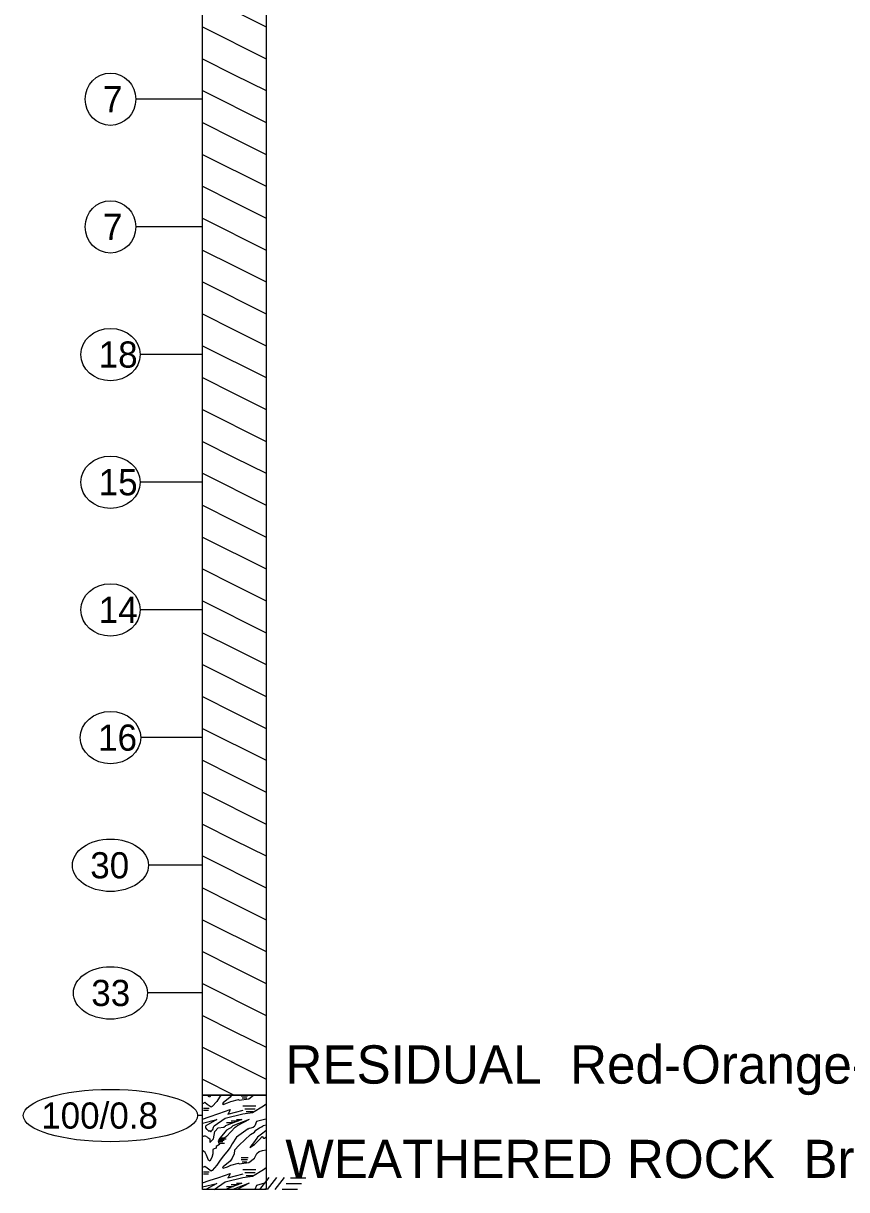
# Model space of a CAD drawing. Extents: x -26 to 303, y -74 to 518.
# Drawn here: x 126.74 to 158.98, y -74.2 to -28.53 of the extents above; entities that cross this region are included whole.
import ezdxf

# ---------------------------------------------------------------- set-up
doc = ezdxf.new("R2010")
doc.units = 0
for name, color, linetype in [('Prop Road Sect_ Boring - Material (Desc Tx)', 7, 'Continuous'), ('Prop Road Sect_ Boring - Material (Outline)', 7, 'Continuous'), ('Prop Road Sect_ Boring - Peripheral (HR Indicator)', 7, 'Continuous'), ('Prop Road Sect_ Boring - Peripheral (SPT Oval + Leader)', 7, 'Continuous'), ('Prop Road Sect_ Boring - Peripheral (SPT Tx)', 7, 'Continuous')]:
    doc.layers.add(name, color=color, linetype=linetype)

msp = doc.modelspace()

# ---------------------------------------------------------------- linework, layer by layer
at = {"layer": 'Prop Road Sect_ Boring - Material (Outline)'}
for p, q in [((134.999, -28.042), (136.248, -28.667)), ((134.999, -28.042), (136.248, -28.667)), ((133.75, -28.667), (136.248, -29.916)), ((133.75, -28.667), (136.248, -29.916)), ((133.75, -28.667), (136.248, -29.916)), ((133.75, -28.667), (136.248, -29.916)), ((136.248, -28.667), (136.25, -28.668)), ((136.248, -28.667), (136.25, -28.668)), ((136.248, -28.667), (136.25, -28.668)), ((136.248, -28.667), (136.25, -28.668)), ((133.75, -29.916), (134.999, -30.54)), ((133.75, -29.916), (134.999, -30.54)), ((136.248, -29.916), (136.25, -29.917)), ((136.248, -29.916), (136.25, -29.917)), ((134.999, -30.54), (136.248, -31.164)), ((134.999, -30.54), (136.248, -31.164)), ((133.75, -31.164), (136.248, -32.413)), ((133.75, -31.164), (136.248, -32.413)), ((133.75, -31.164), (136.248, -32.413)), ((133.75, -31.164), (136.248, -32.413)), ((136.248, -31.164), (136.25, -31.166)), ((136.248, -31.164), (136.25, -31.166)), ((136.248, -31.164), (136.25, -31.166)), ((136.248, -31.164), (136.25, -31.166)), ((133.75, -32.413), (134.999, -33.037)), ((133.75, -32.413), (134.999, -33.037)), ((136.248, -32.413), (136.25, -32.414)), ((136.248, -32.413), (136.25, -32.414)), ((134.999, -33.037), (136.248, -33.662)), ((134.999, -33.037), (136.248, -33.662)), ((133.75, -33.662), (136.248, -34.911)), ((133.75, -33.662), (136.248, -34.911)), ((133.75, -33.662), (136.248, -34.911)), ((133.75, -33.662), (136.248, -34.911)), ((136.248, -33.662), (136.25, -33.663)), ((136.248, -33.662), (136.25, -33.663)), ((136.248, -33.662), (136.25, -33.663)), ((136.248, -33.662), (136.25, -33.663)), ((133.75, -34.911), (134.999, -35.535)), ((133.75, -34.911), (134.999, -35.535)), ((136.248, -34.911), (136.25, -34.912)), ((136.248, -34.911), (136.25, -34.912)), ((134.999, -35.535), (136.248, -36.159)), ((134.999, -35.535), (136.248, -36.159)), ((133.75, -36.159), (136.248, -37.408)), ((133.75, -36.159), (136.248, -37.408)), ((133.75, -36.159), (136.248, -37.408)), ((133.75, -36.159), (136.248, -37.408)), ((136.248, -36.159), (136.25, -36.161)), ((136.248, -36.159), (136.25, -36.161)), ((136.248, -36.159), (136.25, -36.161)), ((136.248, -36.159), (136.25, -36.161)), ((133.75, -37.408), (134.999, -38.032)), ((133.75, -37.408), (134.999, -38.032)), ((136.248, -37.408), (136.25, -37.409)), ((136.248, -37.408), (136.25, -37.409)), ((134.999, -38.032), (136.248, -38.657)), ((134.999, -38.032), (136.248, -38.657)), ((133.75, -38.657), (136.248, -39.906)), ((133.75, -38.657), (136.248, -39.906)), ((133.75, -38.657), (136.248, -39.906)), ((133.75, -38.657), (136.248, -39.906)), ((136.248, -38.657), (136.25, -38.658)), ((136.248, -38.657), (136.25, -38.658)), ((136.248, -38.657), (136.25, -38.658)), ((136.248, -38.657), (136.25, -38.658)), ((133.75, -39.906), (134.999, -40.53)), ((133.75, -39.906), (134.999, -40.53)), ((136.248, -39.906), (136.25, -39.907)), ((136.248, -39.906), (136.25, -39.907)), ((134.999, -40.53), (136.248, -41.154)), ((134.999, -40.53), (136.248, -41.154)), ((133.75, -41.154), (136.248, -42.403)), ((133.75, -41.154), (136.248, -42.403)), ((133.75, -41.154), (136.248, -42.403)), ((133.75, -41.154), (136.248, -42.403)), ((136.248, -41.154), (136.25, -41.156)), ((136.248, -41.154), (136.25, -41.156)), ((136.248, -41.154), (136.25, -41.156)), ((136.248, -41.154), (136.25, -41.156)), ((133.75, -42.403), (134.999, -43.027)), ((133.75, -42.403), (134.999, -43.027)), ((136.248, -42.403), (136.25, -42.404)), ((136.248, -42.403), (136.25, -42.404)), ((134.999, -43.027), (136.248, -43.652)), ((134.999, -43.027), (136.248, -43.652)), ((133.75, -43.652), (136.248, -44.901)), ((133.75, -43.652), (136.248, -44.901)), ((133.75, -43.652), (136.248, -44.901)), ((133.75, -43.652), (136.248, -44.901)), ((136.248, -43.652), (136.25, -43.653)), ((136.248, -43.652), (136.25, -43.653)), ((136.248, -43.652), (136.25, -43.653)), ((136.248, -43.652), (136.25, -43.653)), ((133.75, -44.901), (134.999, -45.525)), ((133.75, -44.901), (134.999, -45.525)), ((136.248, -44.901), (136.25, -44.902)), ((136.248, -44.901), (136.25, -44.902)), ((134.999, -45.525), (136.248, -46.149)), ((134.999, -45.525), (136.248, -46.149)), ((133.75, -46.149), (136.248, -47.398)), ((133.75, -46.149), (136.248, -47.398)), ((133.75, -46.149), (136.248, -47.398)), ((133.75, -46.149), (136.248, -47.398)), ((136.248, -46.149), (136.25, -46.151)), ((136.248, -46.149), (136.25, -46.151)), ((136.248, -46.149), (136.25, -46.151)), ((136.248, -46.149), (136.25, -46.151)), ((133.75, -47.398), (134.999, -48.022)), ((133.75, -47.398), (134.999, -48.022)), ((136.248, -47.398), (136.25, -47.399)), ((136.248, -47.398), (136.25, -47.399)), ((134.999, -48.022), (136.248, -48.647)), ((134.999, -48.022), (136.248, -48.647)), ((133.75, -48.647), (136.248, -49.896)), ((133.75, -48.647), (136.248, -49.896)), ((133.75, -48.647), (136.248, -49.896)), ((133.75, -48.647), (136.248, -49.896)), ((136.248, -48.647), (136.25, -48.648)), ((136.248, -48.647), (136.25, -48.648)), ((136.248, -48.647), (136.25, -48.648)), ((136.248, -48.647), (136.25, -48.648)), ((133.75, -49.896), (134.999, -50.52)), ((133.75, -49.896), (134.999, -50.52)), ((136.248, -49.896), (136.25, -49.897)), ((136.248, -49.896), (136.25, -49.897)), ((134.999, -50.52), (136.248, -51.144)), ((134.999, -50.52), (136.248, -51.144)), ((133.75, -51.144), (136.248, -52.393)), ((133.75, -51.144), (136.248, -52.393)), ((133.75, -51.144), (136.248, -52.393)), ((133.75, -51.144), (136.248, -52.393)), ((136.248, -51.144), (136.25, -51.146)), ((136.248, -51.144), (136.25, -51.146)), ((136.248, -51.144), (136.25, -51.146)), ((136.248, -51.144), (136.25, -51.146)), ((133.75, -52.393), (134.999, -53.017)), ((133.75, -52.393), (134.999, -53.017)), ((136.248, -52.393), (136.25, -52.394)), ((136.248, -52.393), (136.25, -52.394)), ((134.999, -53.017), (136.248, -53.642)), ((134.999, -53.017), (136.248, -53.642)), ((133.75, -53.642), (136.248, -54.891)), ((133.75, -53.642), (136.248, -54.891)), ((133.75, -53.642), (136.248, -54.891)), ((133.75, -53.642), (136.248, -54.891)), ((136.248, -53.642), (136.25, -53.643)), ((136.248, -53.642), (136.25, -53.643)), ((136.248, -53.642), (136.25, -53.643)), ((136.248, -53.642), (136.25, -53.643)), ((133.75, -54.891), (134.999, -55.515)), ((133.75, -54.891), (134.999, -55.515)), ((136.248, -54.891), (136.25, -54.892)), ((136.248, -54.891), (136.25, -54.892)), ((134.999, -55.515), (136.248, -56.139)), ((134.999, -55.515), (136.248, -56.139)), ((133.75, -56.139), (136.248, -57.388)), ((133.75, -56.139), (136.248, -57.388)), ((133.75, -56.139), (136.248, -57.388)), ((133.75, -56.139), (136.248, -57.388)), ((136.248, -56.139), (136.25, -56.141)), ((136.248, -56.139), (136.25, -56.141)), ((136.248, -56.139), (136.25, -56.141)), ((136.248, -56.139), (136.25, -56.141)), ((133.75, -57.388), (134.999, -58.012)), ((133.75, -57.388), (134.999, -58.012)), ((136.248, -57.388), (136.25, -57.389)), ((136.248, -57.388), (136.25, -57.389)), ((134.999, -58.012), (136.248, -58.637)), ((134.999, -58.012), (136.248, -58.637)), ((133.75, -58.637), (136.248, -59.886)), ((133.75, -58.637), (136.248, -59.886)), ((133.75, -58.637), (136.248, -59.886)), ((133.75, -58.637), (136.248, -59.886)), ((136.248, -58.637), (136.25, -58.638)), ((136.248, -58.637), (136.25, -58.638)), ((136.248, -58.637), (136.25, -58.638)), ((136.248, -58.637), (136.25, -58.638)), ((133.75, -59.886), (134.999, -60.51)), ((133.75, -59.886), (134.999, -60.51)), ((136.248, -59.886), (136.25, -59.887)), ((136.248, -59.886), (136.25, -59.887)), ((134.999, -60.51), (136.248, -61.134)), ((134.999, -60.51), (136.248, -61.134)), ((133.75, -61.134), (136.248, -62.383)), ((133.75, -61.134), (136.248, -62.383)), ((133.75, -61.134), (136.248, -62.383)), ((133.75, -61.134), (136.248, -62.383)), ((136.248, -61.134), (136.25, -61.136)), ((136.248, -61.134), (136.25, -61.136)), ((136.248, -61.134), (136.25, -61.136)), ((136.248, -61.134), (136.25, -61.136)), ((133.75, -62.383), (134.999, -63.007)), ((133.75, -62.383), (134.999, -63.007)), ((136.248, -62.383), (136.25, -62.384)), ((136.248, -62.383), (136.25, -62.384)), ((134.999, -63.007), (136.248, -63.632)), ((134.999, -63.007), (136.248, -63.632)), ((133.75, -63.632), (136.248, -64.881)), ((133.75, -63.632), (136.248, -64.881)), ((133.75, -63.632), (136.248, -64.881)), ((133.75, -63.632), (136.248, -64.881)), ((136.248, -63.632), (136.25, -63.633)), ((136.248, -63.632), (136.25, -63.633)), ((136.248, -63.632), (136.25, -63.633)), ((136.248, -63.632), (136.25, -63.633)), ((133.75, -64.881), (134.999, -65.505)), ((133.75, -64.881), (134.999, -65.505)), ((136.248, -64.881), (136.25, -64.882)), ((136.248, -64.881), (136.25, -64.882)), ((134.999, -65.505), (136.248, -66.129)), ((134.999, -65.505), (136.248, -66.129)), ((133.75, -66.129), (136.248, -67.378)), ((133.75, -66.129), (136.248, -67.378)), ((133.75, -66.129), (136.248, -67.378)), ((133.75, -66.129), (136.248, -67.378)), ((136.248, -66.129), (136.25, -66.131)), ((136.248, -66.129), (136.25, -66.131)), ((136.248, -66.129), (136.25, -66.131)), ((136.248, -66.129), (136.25, -66.131)), ((133.75, -67.378), (134.999, -68.002)), ((133.75, -67.378), (134.999, -68.002)), ((136.248, -67.378), (136.25, -67.379)), ((136.248, -67.378), (136.25, -67.379)), ((134.999, -68.002), (136.248, -68.627)), ((134.999, -68.002), (136.248, -68.627)), ((133.75, -68.627), (136.248, -69.876)), ((133.75, -68.627), (136.248, -69.876)), ((133.75, -68.627), (136.248, -69.876)), ((133.75, -68.627), (136.248, -69.876)), ((136.248, -68.627), (136.25, -68.628)), ((136.248, -68.627), (136.25, -68.628)), ((136.248, -68.627), (136.25, -68.628)), ((136.248, -68.627), (136.25, -68.628)), ((133.75, -69.876), (134.999, -70.5)), ((133.75, -69.876), (134.999, -70.5)), ((136.248, -69.876), (136.25, -69.877)), ((136.248, -69.876), (136.25, -69.877)), ((135.264, -70.526), (135.514, -70.526)), ((135.264, -70.526), (135.514, -70.526)), ((135.314, -70.611), (135.489, -70.611)), ((135.314, -70.611), (135.489, -70.611)), ((133.789, -71.005), (134.014, -71.005)), ((133.789, -71.005), (134.014, -71.005)), ((133.789, -71.089), (133.989, -71.089)), ((133.789, -71.089), (133.989, -71.089)), ((135.339, -70.92), (135.839, -70.92)), ((135.339, -70.92), (135.839, -70.92)), ((135.414, -71.032), (135.814, -71.032)), ((135.414, -71.032), (135.814, -71.032)), ((135.464, -71.145), (135.739, -71.145)), ((135.464, -71.145), (135.739, -71.145)), ((136.25, -70.842), (136.248, -70.843)), ((136.25, -70.842), (136.248, -70.843)), ((133.75, -71.596), (134.318, -71.459)), ((133.75, -71.596), (134.318, -71.459)), ((134.318, -71.459), (133.889, -71.702)), ((134.318, -71.459), (133.889, -71.702)), ((134.189, -71.759), (134.21, -71.702)), ((134.189, -71.759), (134.21, -71.702)), ((134.589, -71.759), (134.649, -71.702)), ((134.589, -71.759), (134.649, -71.702)), ((135.289, -71.456), (134.649, -71.702)), ((135.289, -71.456), (134.649, -71.702)), ((134.688, -71.577), (134.974, -71.577)), ((134.688, -71.577), (134.974, -71.577)), ((134.873, -71.509), (135.152, -71.509)), ((134.873, -71.509), (135.152, -71.509)), ((135.585, -71.456), (134.944, -71.702)), ((135.585, -71.456), (134.944, -71.702)), ((135.039, -71.759), (135.107, -71.702)), ((135.039, -71.759), (135.107, -71.702)), ((135.089, -71.456), (135.289, -71.456)), ((135.089, -71.456), (135.289, -71.456)), ((135.585, -71.456), (135.107, -71.702)), ((135.585, -71.456), (135.107, -71.702)), ((136.248, -71.673), (136.134, -71.702)), ((136.248, -71.673), (136.134, -71.702)), ((136.248, -71.438), (136.25, -71.437)), ((136.248, -71.438), (136.25, -71.437)), ((136.248, -71.596), (136.25, -71.595)), ((136.248, -71.596), (136.25, -71.595)), ((136.25, -72.132), (136.248, -72.133)), ((136.25, -72.132), (136.248, -72.133)), ((134.371, -72.316), (134.556, -72.316)), ((134.371, -72.316), (134.556, -72.316)), ((134.388, -72.261), (134.603, -72.261)), ((134.388, -72.261), (134.603, -72.261)), ((134.389, -72.377), (134.614, -72.377)), ((134.389, -72.377), (134.614, -72.377)), ((134.419, -72.214), (134.686, -72.214)), ((134.419, -72.214), (134.686, -72.214)), ((133.856, -72.749), (133.75, -72.663)), ((133.856, -72.749), (133.75, -72.663)), ((135.264, -72.94), (135.539, -72.94)), ((135.264, -72.94), (135.539, -72.94)), ((135.264, -73.024), (135.514, -73.024)), ((135.264, -73.024), (135.514, -73.024)), ((136.25, -72.665), (136.248, -72.663)), ((136.25, -72.665), (136.248, -72.663)), ((133.789, -73.502), (134.014, -73.502)), ((133.789, -73.502), (134.014, -73.502)), ((135.314, -73.109), (135.489, -73.109)), ((135.314, -73.109), (135.489, -73.109)), ((135.339, -73.417), (135.839, -73.417)), ((135.339, -73.417), (135.839, -73.417)), ((135.414, -73.53), (135.814, -73.53)), ((135.414, -73.53), (135.814, -73.53)), ((136.25, -73.339), (136.248, -73.34)), ((136.25, -73.339), (136.248, -73.34)), ((133.75, -74.093), (134.318, -73.956)), ((133.75, -74.093), (134.318, -73.956)), ((133.789, -73.586), (133.989, -73.586)), ((133.789, -73.586), (133.989, -73.586)), ((134.318, -73.956), (133.889, -74.2)), ((134.318, -73.956), (133.889, -74.2)), ((135.289, -73.953), (134.649, -74.2)), ((135.289, -73.953), (134.649, -74.2)), ((135.585, -73.953), (134.944, -74.2)), ((135.585, -73.953), (134.944, -74.2)), ((135.089, -73.953), (135.289, -73.953)), ((135.089, -73.953), (135.289, -73.953)), ((135.585, -73.953), (135.107, -74.2)), ((135.585, -73.953), (135.107, -74.2)), ((135.464, -73.642), (135.739, -73.642)), ((135.464, -73.642), (135.739, -73.642)), ((136.248, -73.936), (136.25, -73.935)), ((136.248, -73.936), (136.25, -73.935)), ((134.688, -74.075), (134.974, -74.075)), ((134.688, -74.075), (134.974, -74.075)), ((134.873, -74.006), (135.152, -74.006)), ((134.873, -74.006), (135.152, -74.006)), ((136.248, -74.171), (136.134, -74.2)), ((136.248, -74.171), (136.134, -74.2)), ((136.248, -74.093), (136.25, -74.092)), ((136.248, -74.093), (136.25, -74.092))]:
    msp.add_line(p, q, dxfattribs=at)
for points in [[(133.75, -15.5), (136.25, -15.5), (136.25, -70.5), (133.75, -70.5)], [(133.75, -70.5), (136.25, -70.5), (136.25, -74.2), (133.75, -74.2)]]:
    msp.add_lwpolyline(points, close=True, dxfattribs=at)
for points in [[(134.477, -70.5), (134.414, -70.582), (134.314, -70.751), (134.139, -70.949), (134.089, -70.976), (133.939, -70.864)], [(134.477, -70.5), (134.414, -70.582), (134.314, -70.751), (134.139, -70.949), (134.089, -70.976), (133.939, -70.864)], [(134.083, -70.5), (134.039, -70.582), (133.989, -70.555), (133.968, -70.5)], [(134.083, -70.5), (134.039, -70.582), (133.989, -70.555), (133.968, -70.5)], [(134.894, -70.5), (134.839, -70.582), (134.564, -70.807), (134.539, -70.836), (134.564, -70.864), (134.739, -70.807), (134.864, -70.751), (135.164, -70.667), (135.189, -70.695), (135.564, -70.639), (135.749, -70.5)], [(134.894, -70.5), (134.839, -70.582), (134.564, -70.807), (134.539, -70.836), (134.564, -70.864), (134.739, -70.807), (134.864, -70.751), (135.164, -70.667), (135.189, -70.695), (135.564, -70.639), (135.749, -70.5)], [(133.939, -70.864), (133.846, -70.794), (133.75, -70.843)], [(133.939, -70.864), (133.846, -70.794), (133.75, -70.843)], [(133.75, -71.438), (134.018, -71.345), (134.396, -71.222), (134.843, -71.069), (134.788, -71.191), (134.745, -71.242), (135.342, -71.087)], [(133.75, -71.438), (134.018, -71.345), (134.396, -71.222), (134.843, -71.069), (134.788, -71.191), (134.745, -71.242), (135.342, -71.087)], [(134.21, -71.702), (134.639, -71.399), (135.339, -71.23), (135.714, -71.174), (136.139, -70.92), (136.248, -70.841)], [(134.21, -71.702), (134.639, -71.399), (135.339, -71.23), (135.714, -71.174), (136.139, -70.92), (136.248, -70.841)], [(133.939, -71.842), (133.889, -71.786), (133.889, -71.702)], [(133.939, -71.842), (133.889, -71.786), (133.889, -71.702)], [(134.944, -71.702), (134.858, -71.782), (134.81, -71.806), (134.698, -71.877), (134.624, -71.954), (134.51, -72.091), (134.439, -72.18)], [(134.944, -71.702), (134.858, -71.782), (134.81, -71.806), (134.698, -71.877), (134.624, -71.954), (134.51, -72.091), (134.439, -72.18)], [(135.539, -71.815), (135.586, -71.796), (135.656, -71.781), (135.743, -71.754), (135.798, -71.702)], [(135.539, -71.815), (135.586, -71.796), (135.656, -71.781), (135.743, -71.754), (135.798, -71.702)], [(136.248, -71.44), (136.189, -71.455), (135.864, -71.539), (135.798, -71.702)], [(136.248, -71.44), (136.189, -71.455), (135.864, -71.539), (135.798, -71.702)], [(136.039, -71.759), (136.071, -71.741), (136.134, -71.702)], [(136.039, -71.759), (136.071, -71.741), (136.134, -71.702)], [(133.968, -72.159), (133.87, -72.11), (133.803, -72.11), (133.75, -72.133)], [(133.968, -72.159), (133.87, -72.11), (133.803, -72.11), (133.75, -72.133)], [(135.039, -71.759), (134.689, -72.124), (134.614, -72.18), (134.439, -72.18), (134.364, -72.292), (134.389, -72.377), (134.414, -72.434), (134.289, -72.517), (134.289, -72.574), (134.289, -72.574), (134.214, -72.602), (134.164, -72.63), (134.164, -72.799), (134.114, -72.94), (134.039, -73.08), (133.989, -73.052), (133.914, -72.855), (133.856, -72.749)], [(135.039, -71.759), (134.689, -72.124), (134.614, -72.18), (134.439, -72.18), (134.364, -72.292), (134.389, -72.377), (134.414, -72.434), (134.289, -72.517), (134.289, -72.574), (134.289, -72.574), (134.214, -72.602), (134.164, -72.63), (134.164, -72.799), (134.114, -72.94), (134.039, -73.08), (133.989, -73.052), (133.914, -72.855), (133.856, -72.749)], [(133.939, -71.842), (133.964, -71.871), (134.014, -71.927), (134.039, -71.871), (134.064, -71.927), (134.089, -71.927), (134.114, -71.871), (134.164, -71.842), (134.189, -71.759)], [(133.939, -71.842), (133.964, -71.871), (134.014, -71.927), (134.039, -71.871), (134.064, -71.927), (134.089, -71.927), (134.114, -71.871), (134.164, -71.842), (134.189, -71.759)], [(135.539, -71.815), (135.089, -72.152), (134.914, -72.405), (134.839, -72.546), (134.714, -72.715), (134.564, -72.884), (134.414, -73.08), (134.314, -73.249), (134.139, -73.446), (134.089, -73.474), (133.939, -73.361)], [(135.539, -71.815), (135.089, -72.152), (134.914, -72.405), (134.839, -72.546), (134.714, -72.715), (134.564, -72.884), (134.414, -73.08), (134.314, -73.249), (134.139, -73.446), (134.089, -73.474), (133.939, -73.361)], [(133.968, -72.159), (134.039, -72.209), (134.039, -72.349), (134.189, -72.209), (134.239, -71.927), (134.364, -71.786), (134.589, -71.759)], [(133.968, -72.159), (134.039, -72.209), (134.039, -72.349), (134.189, -72.209), (134.239, -71.927), (134.364, -71.786), (134.589, -71.759)], [(135.639, -72.04), (135.189, -72.461), (135.014, -72.659), (134.989, -72.799), (134.914, -72.967), (134.839, -73.08), (134.564, -73.305), (134.539, -73.334), (134.564, -73.361), (134.739, -73.305), (134.864, -73.249), (135.164, -73.165), (135.189, -73.192), (135.564, -73.136), (135.789, -72.967), (135.886, -72.792)], [(135.639, -72.04), (135.189, -72.461), (135.014, -72.659), (134.989, -72.799), (134.914, -72.967), (134.839, -73.08), (134.564, -73.305), (134.539, -73.334), (134.564, -73.361), (134.739, -73.305), (134.864, -73.249), (135.164, -73.165), (135.189, -73.192), (135.564, -73.136), (135.789, -72.967), (135.886, -72.792)], [(136.248, -71.883), (136.114, -71.984), (135.914, -72.152), (135.789, -72.321), (135.614, -72.546), (135.789, -72.434), (135.989, -72.236), (136.089, -72.124), (136.139, -72.18), (136.189, -72.18), (136.248, -72.128)], [(136.248, -71.883), (136.114, -71.984), (135.914, -72.152), (135.789, -72.321), (135.614, -72.546), (135.789, -72.434), (135.989, -72.236), (136.089, -72.124), (136.139, -72.18), (136.189, -72.18), (136.248, -72.128)], [(135.639, -72.04), (135.789, -71.955), (135.839, -71.871), (135.989, -71.786), (136.039, -71.759)], [(135.639, -72.04), (135.789, -71.955), (135.839, -71.871), (135.989, -71.786), (136.039, -71.759)], [(135.886, -72.792), (135.969, -72.71), (136.11, -72.672), (136.248, -72.646)], [(135.886, -72.792), (135.969, -72.71), (136.11, -72.672), (136.248, -72.646)], [(133.939, -73.361), (133.846, -73.291), (133.75, -73.34)], [(133.939, -73.361), (133.846, -73.291), (133.75, -73.34)], [(134.21, -74.2), (134.639, -73.896), (135.339, -73.727), (135.714, -73.671), (136.139, -73.417), (136.248, -73.339)], [(134.21, -74.2), (134.639, -73.896), (135.339, -73.727), (135.714, -73.671), (136.139, -73.417), (136.248, -73.339)], [(133.75, -73.936), (134.018, -73.842), (134.396, -73.72), (134.843, -73.566), (134.788, -73.689), (134.745, -73.74), (135.342, -73.584)], [(133.75, -73.936), (134.018, -73.842), (134.396, -73.72), (134.843, -73.566), (134.788, -73.689), (134.745, -73.74), (135.342, -73.584)], [(136.248, -73.938), (136.189, -73.952), (135.864, -74.036), (135.798, -74.2)], [(136.248, -73.938), (136.189, -73.952), (135.864, -74.036), (135.798, -74.2)]]:
    msp.add_lwpolyline(points, dxfattribs=at)
at = {"layer": 'Prop Road Sect_ Boring - Peripheral (HR Indicator)'}
for p, q in [((136, -74.2), (136.361, -73.721)), ((136.3, -74.2), (136.661, -73.721)), ((136.6, -74.2), (136.961, -73.721)), ((137.037, -73.961), (137.637, -73.961)), ((137.205, -73.738), (137.805, -73.738)), ((136.869, -74.183), (137.469, -74.183))]:
    msp.add_line(p, q, dxfattribs=at)
at = {"layer": 'Prop Road Sect_ Boring - Peripheral (SPT Oval + Leader)'}
for p, q in [((133.75, -31.5), (131.141, -31.5)), ((133.75, -36.5), (131.141, -36.5)), ((133.75, -41.5), (131.31, -41.5)), ((133.75, -46.5), (131.31, -46.5)), ((133.75, -51.5), (131.31, -51.5)), ((133.75, -56.5), (131.334, -56.5)), ((133.75, -61.5), (131.641, -61.5)), ((133.75, -66.5), (131.601, -66.5)), ((133.75, -71.3), (133.562, -71.3))]:
    msp.add_line(p, q, dxfattribs=at)
for centre, major_axis, ratio in [((130.15, -31.5), (0, 1.025), 0.966391), ((130.15, -36.5), (0, 1.025), 0.966391), ((130.15, -41.5), (1.16, 0), 0.883591), ((130.15, -46.5), (1.16, 0), 0.883591), ((130.15, -51.5), (1.16, 0), 0.883591), ((130.15, -56.5), (1.184, 0), 0.865525), ((130.15, -61.5), (1.491, 0), 0.687483), ((130.15, -66.5), (1.451, 0), 0.706609), ((130.15, -71.3), (3.412, 0), 0.300427)]:
    msp.add_ellipse(centre, major_axis=major_axis, ratio=ratio, dxfattribs=at)

# ---------------------------------------------------------------- texts
at = {"layer": 'Prop Road Sect_ Boring - Material (Desc Tx)'}
for s, p in [('RESIDUAL  Red-Orange-Yellow, Sandy Silty CLAY', (137, -70.05)), ('WEATHERED ROCK  Brown-Gray (META-ARGILLITE)', (137, -73.75))]:
    msp.add_text(s, height=1.5, dxfattribs=at).set_placement(p)
at = {"layer": 'Prop Road Sect_ Boring - Peripheral (SPT Tx)'}
for s, p in [('7', (129.859, -32.012)), ('7', (129.859, -37.012)), ('18', (129.69, -42.012)), ('15', (129.69, -47.012)), ('14', (129.69, -52.012)), ('16', (129.666, -57.012)), ('30', (129.359, -62.012)), ('33', (129.399, -67.012)), ('100/0.8', (127.438, -71.812))]:
    msp.add_text(s, height=1.025, dxfattribs=at).set_placement(p)

doc.saveas('drawing.dxf')
